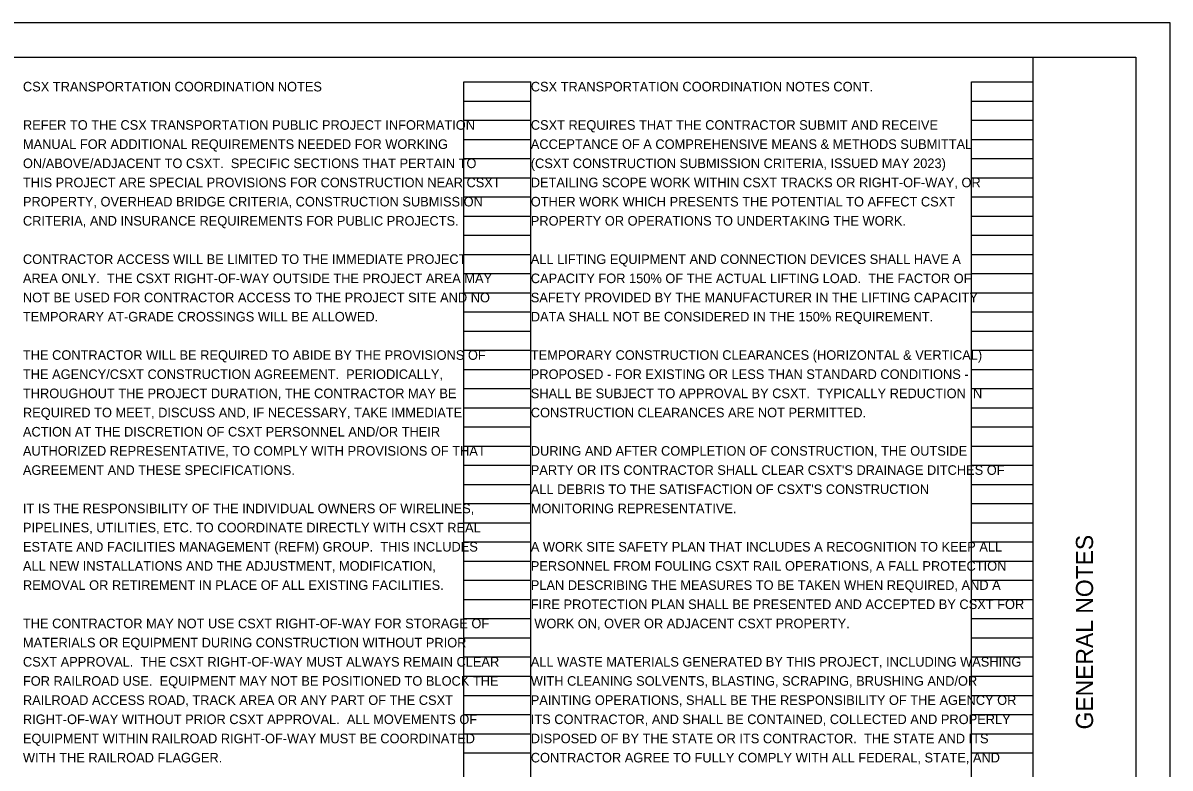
# Model space of a CAD drawing. Extents: x 0 to 34, y 0 to 22.
# Drawn here: x 17.24 to 34, y 11.12 to 22 of the extents above; entities that cross this region are included whole.
import ezdxf

# ---------------------------------------------------------------- set-up
doc = ezdxf.new("R2010")
doc.units = 0
for name, color, linetype in [('SH_Border', 7, 'Continuous'), ('SH_Cut_Line', 7, 'Continuous'), ('SH_Data', 7, 'Continuous'), ('SH_Text', 7, 'Continuous')]:
    doc.layers.add(name, color=color, linetype=linetype)

msp = doc.modelspace()

# ---------------------------------------------------------------- linework, layer by layer
at = {"layer": 'SH_Border'}
msp.add_line((32, 0.5), (32, 21.5), dxfattribs=at)
msp.add_lwpolyline([(1.5, 21.5), (33.5, 21.5), (33.5, 0.5), (1.5, 0.5)], close=True, dxfattribs=at)
at = {"layer": 'SH_Cut_Line'}
msp.add_lwpolyline([(0, 0), (34, 0), (34, 22), (0, 22)], close=True, dxfattribs=at)
at = {"layer": 'SH_Data'}
for p, q in [((23.68, 0.98), (23.68, 21.14)), ((23.68, 21.14), (24.66, 21.14)), ((24.66, 0.98), (24.66, 21.14)), ((31.1, 0.98), (31.1, 21.14)), ((31.1, 21.14), (32, 21.14)), ((32, 0.98), (32, 21.14)), ((23.68, 20.86), (24.66, 20.86)), ((31.1, 20.86), (32, 20.86)), ((23.68, 20.58), (24.66, 20.58)), ((31.1, 20.58), (32, 20.58)), ((23.68, 20.3), (24.66, 20.3)), ((31.1, 20.3), (32, 20.3)), ((23.68, 20.02), (24.66, 20.02)), ((31.1, 20.02), (32, 20.02)), ((23.68, 19.74), (24.66, 19.74)), ((31.1, 19.74), (32, 19.74)), ((23.68, 19.46), (24.66, 19.46)), ((31.1, 19.46), (32, 19.46)), ((23.68, 19.18), (24.66, 19.18)), ((31.1, 19.18), (32, 19.18)), ((23.68, 18.9), (24.66, 18.9)), ((31.1, 18.9), (32, 18.9)), ((23.68, 18.62), (24.66, 18.62)), ((31.1, 18.62), (32, 18.62)), ((23.68, 18.34), (24.66, 18.34)), ((31.1, 18.34), (32, 18.34)), ((23.68, 18.06), (24.66, 18.06)), ((31.1, 18.06), (32, 18.06)), ((23.68, 17.78), (24.66, 17.78)), ((31.1, 17.78), (32, 17.78)), ((23.68, 17.5), (24.66, 17.5)), ((31.1, 17.5), (32, 17.5)), ((23.68, 17.22), (24.66, 17.22)), ((31.1, 17.22), (32, 17.22)), ((23.68, 16.94), (24.66, 16.94)), ((31.1, 16.94), (32, 16.94)), ((23.68, 16.66), (24.66, 16.66)), ((31.1, 16.66), (32, 16.66)), ((23.68, 16.38), (24.66, 16.38)), ((31.1, 16.38), (32, 16.38)), ((23.68, 16.1), (24.66, 16.1)), ((31.1, 16.1), (32, 16.1)), ((23.68, 15.82), (24.66, 15.82)), ((31.1, 15.82), (32, 15.82)), ((23.68, 15.54), (24.66, 15.54)), ((31.1, 15.54), (32, 15.54)), ((23.68, 15.26), (24.66, 15.26)), ((31.1, 15.26), (32, 15.26)), ((23.68, 14.98), (24.66, 14.98)), ((31.1, 14.98), (32, 14.98)), ((23.68, 14.7), (24.66, 14.7)), ((31.1, 14.7), (32, 14.7)), ((23.68, 14.42), (24.66, 14.42)), ((31.1, 14.42), (32, 14.42)), ((23.68, 14.14), (24.66, 14.14)), ((31.1, 14.14), (32, 14.14)), ((23.68, 13.86), (24.66, 13.86)), ((31.1, 13.86), (32, 13.86)), ((23.68, 13.58), (24.66, 13.58)), ((31.1, 13.58), (32, 13.58)), ((23.68, 13.3), (24.66, 13.3)), ((31.1, 13.3), (32, 13.3)), ((23.68, 13.02), (24.66, 13.02)), ((31.1, 13.02), (32, 13.02)), ((23.68, 12.74), (24.66, 12.74)), ((31.1, 12.74), (32, 12.74)), ((23.68, 12.46), (24.66, 12.46)), ((31.1, 12.46), (32, 12.46)), ((23.68, 12.18), (24.66, 12.18)), ((31.1, 12.18), (32, 12.18)), ((23.68, 11.9), (24.66, 11.9)), ((31.1, 11.9), (32, 11.9)), ((23.68, 11.62), (24.66, 11.62)), ((31.1, 11.62), (32, 11.62)), ((23.68, 11.34), (24.66, 11.34)), ((31.1, 11.34), (32, 11.34))]:
    msp.add_line(p, q, dxfattribs=at)

# ---------------------------------------------------------------- texts
msp.add_text('GENERAL NOTES', height=0.25, rotation=90, dxfattribs=at).set_placement((32.875, 11.682))
at = {"layer": 'SH_Text'}
for s, p in [('CSX TRANSPORTATION COORDINATION NOTES', (17.24, 21)), ('CSX TRANSPORTATION COORDINATION NOTES CONT.', (24.66, 21)), ('REFER TO THE CSX TRANSPORTATION PUBLIC PROJECT INFORMATION ', (17.24, 20.44)), ('CSXT REQUIRES THAT THE CONTRACTOR SUBMIT AND RECEIVE ', (24.66, 20.44)), ('MANUAL FOR ADDITIONAL REQUIREMENTS NEEDED FOR WORKING ', (17.24, 20.16)), ('ACCEPTANCE OF A COMPREHENSIVE MEANS & METHODS SUBMITTAL ', (24.66, 20.16)), ('ON/ABOVE/ADJACENT TO CSXT.  SPECIFIC SECTIONS THAT PERTAIN TO ', (17.24, 19.88)), ('(CSXT CONSTRUCTION SUBMISSION CRITERIA, ISSUED MAY 2023) ', (24.66, 19.88)), ('THIS PROJECT ARE SPECIAL PROVISIONS FOR CONSTRUCTION NEAR CSXT', (17.24, 19.6)), ('DETAILING SCOPE WORK WITHIN CSXT TRACKS OR RIGHT-OF-WAY, OR ', (24.66, 19.6)), ('PROPERTY, OVERHEAD BRIDGE CRITERIA, CONSTRUCTION SUBMISSION', (17.24, 19.32)), ('OTHER WORK WHICH PRESENTS THE POTENTIAL TO AFFECT CSXT ', (24.66, 19.32)), ('CRITERIA, AND INSURANCE REQUIREMENTS FOR PUBLIC PROJECTS.', (17.24, 19.04)), ('PROPERTY OR OPERATIONS TO UNDERTAKING THE WORK.', (24.66, 19.04)), ('CONTRACTOR ACCESS WILL BE LIMITED TO THE IMMEDIATE PROJECT ', (17.24, 18.48)), ('ALL LIFTING EQUIPMENT AND CONNECTION DEVICES SHALL HAVE A ', (24.66, 18.48)), ('AREA ONLY.  THE CSXT RIGHT-OF-WAY OUTSIDE THE PROJECT AREA MAY', (17.24, 18.2)), ('CAPACITY FOR 150% OF THE ACTUAL LIFTING LOAD.  THE FACTOR OF ', (24.66, 18.2)), ('NOT BE USED FOR CONTRACTOR ACCESS TO THE PROJECT SITE AND NO ', (17.24, 17.92)), ('SAFETY PROVIDED BY THE MANUFACTURER IN THE LIFTING CAPACITY ', (24.66, 17.92)), ('TEMPORARY AT-GRADE CROSSINGS WILL BE ALLOWED.', (17.24, 17.64)), ('DATA SHALL NOT BE CONSIDERED IN THE 150% REQUIREMENT.', (24.66, 17.64)), ('THE CONTRACTOR WILL BE REQUIRED TO ABIDE BY THE PROVISIONS OF ', (17.24, 17.08)), ('TEMPORARY CONSTRUCTION CLEARANCES (HORIZONTAL & VERTICAL) ', (24.66, 17.08)), ('THE AGENCY/CSXT CONSTRUCTION AGREEMENT.  PERIODICALLY, ', (17.24, 16.8)), ('PROPOSED - FOR EXISTING OR LESS THAN STANDARD CONDITIONS - ', (24.66, 16.8)), ('THROUGHOUT THE PROJECT DURATION, THE CONTRACTOR MAY BE ', (17.24, 16.52)), ('SHALL BE SUBJECT TO APPROVAL BY CSXT.  TYPICALLY REDUCTION IN ', (24.66, 16.52)), ('REQUIRED TO MEET, DISCUSS AND, IF NECESSARY, TAKE IMMEDIATE ', (17.24, 16.24)), ('CONSTRUCTION CLEARANCES ARE NOT PERMITTED.', (24.66, 16.24)), ('ACTION AT THE DISCRETION OF CSXT PERSONNEL AND/OR THEIR ', (17.24, 15.96)), ('AUTHORIZED REPRESENTATIVE, TO COMPLY WITH PROVISIONS OF THAT ', (17.24, 15.68)), ('DURING AND AFTER COMPLETION OF CONSTRUCTION, THE OUTSIDE ', (24.66, 15.68)), ('AGREEMENT AND THESE SPECIFICATIONS.', (17.24, 15.4)), ("PARTY OR ITS CONTRACTOR SHALL CLEAR CSXT'S DRAINAGE DITCHES OF ", (24.66, 15.4)), ("ALL DEBRIS TO THE SATISFACTION OF CSXT'S CONSTRUCTION ", (24.66, 15.12)), ('IT IS THE RESPONSIBILITY OF THE INDIVIDUAL OWNERS OF WIRELINES, ', (17.24, 14.84)), ('MONITORING REPRESENTATIVE.', (24.66, 14.84)), ('PIPELINES, UTILITIES, ETC. TO COORDINATE DIRECTLY WITH CSXT REAL', (17.24, 14.56)), ('ESTATE AND FACILITIES MANAGEMENT (REFM) GROUP.  THIS INCLUDES', (17.24, 14.28)), ('A WORK SITE SAFETY PLAN THAT INCLUDES A RECOGNITION TO KEEP ALL ', (24.66, 14.28)), ('ALL NEW INSTALLATIONS AND THE ADJUSTMENT, MODIFICATION, ', (17.24, 14)), ('PERSONNEL FROM FOULING CSXT RAIL OPERATIONS, A FALL PROTECTION ', (24.66, 14)), ('REMOVAL OR RETIREMENT IN PLACE OF ALL EXISTING FACILITIES.', (17.24, 13.72)), ('PLAN DESCRIBING THE MEASURES TO BE TAKEN WHEN REQUIRED, AND A ', (24.66, 13.72)), ('FIRE PROTECTION PLAN SHALL BE PRESENTED AND ACCEPTED BY CSXT FOR', (24.66, 13.44)), ('THE CONTRACTOR MAY NOT USE CSXT RIGHT-OF-WAY FOR STORAGE OF ', (17.24, 13.16)), (' WORK ON, OVER OR ADJACENT CSXT PROPERTY.', (24.66, 13.16)), ('MATERIALS OR EQUIPMENT DURING CONSTRUCTION WITHOUT PRIOR ', (17.24, 12.88)), ('CSXT APPROVAL.  THE CSXT RIGHT-OF-WAY MUST ALWAYS REMAIN CLEAR ', (17.24, 12.6)), ('ALL WASTE MATERIALS GENERATED BY THIS PROJECT, INCLUDING WASHING ', (24.66, 12.6)), ('FOR RAILROAD USE.  EQUIPMENT MAY NOT BE POSITIONED TO BLOCK THE ', (17.24, 12.32)), ('WITH CLEANING SOLVENTS, BLASTING, SCRAPING, BRUSHING AND/OR ', (24.66, 12.32)), ('RAILROAD ACCESS ROAD, TRACK AREA OR ANY PART OF THE CSXT ', (17.24, 12.04)), ('PAINTING OPERATIONS, SHALL BE THE RESPONSIBILITY OF THE AGENCY OR ', (24.66, 12.04)), ('RIGHT-OF-WAY WITHOUT PRIOR CSXT APPROVAL.  ALL MOVEMENTS OF ', (17.24, 11.76)), ('ITS CONTRACTOR, AND SHALL BE CONTAINED, COLLECTED AND PROPERLY ', (24.66, 11.76)), ('EQUIPMENT WITHIN RAILROAD RIGHT-OF-WAY MUST BE COORDINATED ', (17.24, 11.48)), ('DISPOSED OF BY THE STATE OR ITS CONTRACTOR.  THE STATE AND ITS ', (24.66, 11.48)), ('WITH THE RAILROAD FLAGGER.', (17.24, 11.2)), ('CONTRACTOR AGREE TO FULLY COMPLY WITH ALL FEDERAL, STATE, AND ', (24.66, 11.2))]:
    msp.add_text(s, height=0.14, dxfattribs=at).set_placement(p)

doc.saveas('drawing.dxf')
